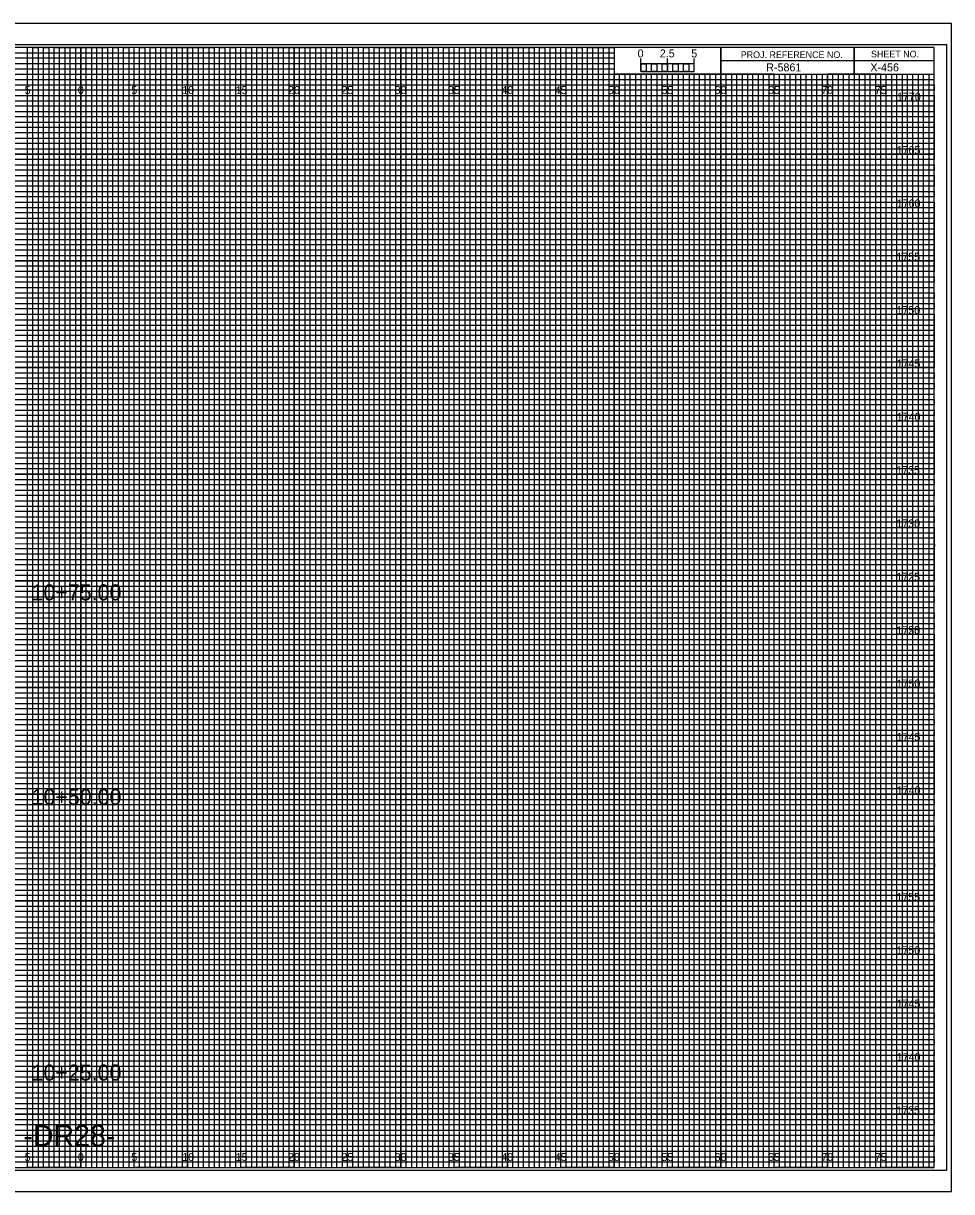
# Model space of a CAD drawing. Extents: x -7 to 162, y -2 to 547.
# Drawn here: x 74.6 to 161.7, y -2.3 to 107.3 of the extents above; entities that cross this region are included whole.
import ezdxf

# ---------------------------------------------------------------- set-up
doc = ezdxf.new("R2010")
doc.units = 0
for name, color, linetype in [('Prop Horizontal Alignment', 7, 'Continuous'), ('Prop XS Alignment Label', 7, 'Continuous'), ('Prop XS Bar Scale Labels', 7, 'Continuous'), ('Prop XS Gore Control Minimum', 7, 'Continuous'), ('Prop XS Project Number', 7, 'Continuous'), ('Prop XS Sheet Number', 7, 'Continuous'), ('Prop XS Shoulder Borrow Shape', 7, 'Continuous'), ('Raster_Level_0', 7, 'Continuous'), ('Scratch_Level_3', 7, 'Continuous'), ('Sheet Cross Section CELL', 7, 'Continuous'), ('Sheet Cross Section Grid Minor 1 CELL', 7, 'Continuous'), ('Sheet Cross Section Grid Minor 2 CELL', 7, 'Continuous'), ('Sheet Cross Section Scale CELL', 7, 'Continuous'), ('Sheet Cutting Line CELL', 7, 'Continuous'), ('Sheet DOT Grid CELL', 7, 'Continuous'), ('Sheet Plot Border Inside CELL', 7, 'Continuous'), ('Sheet Plot Border Outside CELL', 7, 'Continuous')]:
    doc.layers.add(name, color=color, linetype=linetype)

msp = doc.modelspace()

# ---------------------------------------------------------------- linework, layer by layer
at = {"layer": 'Prop XS Gore Control Minimum'}
for p, q in [((75, 105), (70, 105)), ((75, 0), (75, 105)), ((85, 105), (80, 105)), ((80, 105), (80, 0)), ((85, 0), (85, 105)), ((95, 105), (90, 105)), ((90, 105), (90, 0)), ((95, 0), (95, 105)), ((105, 105), (100, 105)), ((100, 105), (100, 0)), ((105, 0), (105, 105)), ((115, 105), (110, 105)), ((110, 105), (110, 0)), ((115, 0), (115, 105)), ((125, 105), (120, 105)), ((120, 105), (120, 0)), ((125, 0), (125, 105)), ((130, 105), (130, 0)), ((135, 0), (135, 102.5)), ((145, 102.5), (140, 102.5)), ((140, 102.5), (140, 0)), ((145, 0), (145, 102.5)), ((155, 102.5), (150, 102.5)), ((150, 102.5), (150, 0)), ((155, 0), (155, 102.5)), ((80, 0), (75, 0)), ((90, 0), (85, 0)), ((100, 0), (95, 0)), ((110, 0), (105, 0)), ((120, 0), (115, 0)), ((130, 0), (125, 0)), ((140, 0), (135, 0)), ((150, 0), (145, 0)), ((160, 0), (155, 0)), ((160, 0), (160, 0))]:
    msp.add_line(p, q, dxfattribs=at)
for points in [[(0, 100), (160, 100), (160, 95), (0, 95)], [(0, 90), (160, 90), (160, 85), (0, 85)], [(0, 80), (160, 80), (160, 75), (0, 75)], [(0, 70), (160, 70), (160, 65), (0, 65)], [(0, 60), (160, 60), (160, 55), (0, 55)], [(0, 50), (160, 50), (160, 45), (0, 45)], [(0, 40), (160, 40), (160, 35), (0, 35)], [(0, 30), (160, 30), (160, 25), (0, 25)], [(0, 20), (160, 20), (160, 15), (0, 15)], [(0, 10), (160, 10), (160, 5), (0, 5)]]:
    msp.add_lwpolyline(points, dxfattribs=at)
at = {"layer": 'Prop XS Shoulder Borrow Shape'}
for points in [[(72.5, 0), (77.5, 0), (77.5, 105), (82.5, 105), (82.5, 0), (87.5, 0), (87.5, 105), (92.5, 105), (92.5, 0), (97.5, 0), (97.5, 105), (102.5, 105), (102.5, 0), (107.5, 0), (107.5, 105), (112.5, 105), (112.5, 0), (117.5, 0), (117.5, 105), (122.5, 105), (122.5, 0), (127.5, 0), (127.5, 105), (129.97, 105), (130, 105), (130, 102.5), (132.5, 102.5), (132.5, 0), (137.5, 0), (137.5, 102.5), (142.5, 102.5), (142.5, 0), (147.5, 0), (147.5, 102.5), (152.5, 102.5), (152.5, 0), (157.5, 0), (157.5, 102.5)], [(0, 102.5), (137.5, 102.5)], [(0, 92.5), (160, 92.5), (160, 97.5), (0, 97.5)], [(0, 82.5), (160, 82.5), (160, 87.5), (0, 87.5)], [(0, 72.5), (160, 72.5), (160, 77.5), (0, 77.5)], [(0, 62.5), (160, 62.5), (160, 67.5), (0, 67.5)], [(0, 52.5), (160, 52.5), (160, 57.5), (0, 57.5)], [(0, 42.5), (160, 42.5), (160, 47.5), (0, 47.5)], [(0, 32.5), (160, 32.5), (160, 37.5), (0, 37.5)], [(0, 22.5), (160, 22.5), (160, 27.5), (0, 27.5)], [(0, 12.5), (160, 12.5), (160, 17.5), (0, 17.5)], [(0, 2.5), (160, 2.5), (160, 7.5), (0, 7.5)]]:
    msp.add_lwpolyline(points, dxfattribs=at)
at = {"layer": 'Sheet Cross Section CELL'}
for p, q in [((152.5, 105), (152.5, 102.5)), ((152.5, 102.5), (152.5, 105)), ((160, 103.75), (140, 103.75)), ((140, 103.75), (140, 102.5)), ((140, 102.5), (160, 102.5))]:
    msp.add_line(p, q, dxfattribs=at)
for points in [[(160, 105), (0, 105), (0, 0), (160, 0)], [(140, 105), (130, 105), (130, 102.52), (140, 102.52)], [(160, 105), (140, 105), (140, 102.5), (160, 102.5)]]:
    msp.add_lwpolyline(points, close=True, dxfattribs=at)
at = {"layer": 'Sheet Cross Section Grid Minor 1 CELL'}
for p, q in [((0, 104.5), (130, 104.5)), ((130, 104.5), (130, 103.99)), ((130, 103.99), (0, 103.99)), ((0, 103.5), (130, 103.5)), ((130, 102.95), (0, 102.95)), ((130, 103.5), (130, 102.95)), ((0, 102), (160, 102))]:
    msp.add_line(p, q, dxfattribs=at)
for points in [[(0, 101.5), (135, 101.5), (160, 101.5), (160, 101), (0, 101)], [(0, 100.5), (160, 100.5), (160, 99.5), (0, 99.5)], [(0, 99), (160, 99), (160, 98.5), (0, 98.49)], [(0, 98), (160, 98), (160, 97), (0, 97)], [(0, 96.5), (160, 96.5), (160, 96), (0, 96)], [(0, 95.5), (160, 95.5), (160, 94.5), (0, 94.5)], [(0, 94), (160, 94), (160, 93.5), (0, 93.5)], [(0, 93), (160, 93), (160, 92), (0, 92)], [(0, 91.5), (160, 91.5), (160, 91), (0, 91)], [(0, 90.5), (160, 90.5), (160, 89.5), (0, 89.5)], [(0, 89), (160, 89), (160, 88.5), (0, 88.5)], [(0, 88), (160, 88), (160, 86.98), (160, 86.5), (160, 86), (0, 86)], [(0, 87), (160, 87), (160, 86.5), (0, 86.5)], [(0, 85.5), (160, 85.5), (160, 84.5), (0, 84.52)], [(0, 84.52), (160, 84.5), (160, 84), (0, 84)], [(0, 83.5), (160, 83.5), (160, 83), (0, 83)], [(0, 82), (160, 82), (160, 81.5), (0, 81.5)], [(0, 81), (160, 81), (160, 80.5), (0, 80.5)], [(-0.04, 79.45), (160, 79.45), (160, 78.94), (-0.04, 78.94)], [(0, 78.5), (160, 78.5), (160, 78), (0, 78)], [(0, 77), (160, 77), (160, 76.5), (0, 76.5)], [(0, 76), (160, 76), (160, 75.5), (0, 75.5)], [(0, 74.5), (160, 74.5), (160, 74), (0, 74)], [(0, 73.5), (160, 73.5), (160, 73), (0, 73)], [(0, 72), (160, 72), (160, 71.5), (0, 71.5)], [(0, 71), (160, 71), (160, 70.5), (0, 70.5)], [(0, 69.5), (160, 69.5), (160, 68.99), (0, 69)], [(0, 68.5), (160, 68.5), (160, 68), (0, 68)], [(0, 67), (160, 67), (160, 66.5), (0, 66.5)], [(0, 66), (160, 66), (160, 65.5), (0, 65.5)], [(0, 64.5), (160, 64.5), (160, 64), (0, 64)], [(0, 63.5), (160, 63.5), (160, 63), (0, 63)], [(0, 62), (160, 62), (160, 61.5), (0, 61.5)], [(0, 61), (160, 61), (160, 60.5), (0, 60.5)], [(0, 59.5), (160, 59.5), (160, 59), (0, 59)], [(0, 58.5), (160.03, 58.45), (160, 58), (0, 58)], [(0, 57), (160, 57), (160, 56.5), (0, 56.5)], [(0, 56), (160, 56), (160, 55.5), (0, 55.5)], [(0, 54.5), (160, 54.5), (160, 54), (0, 54)], [(0, 53.5), (160, 53.5), (160, 53), (0, 53)], [(0, 52), (160, 52), (160, 51.5), (0, 51.5)], [(0, 51), (160, 51), (160, 50.5), (0, 50.5)], [(0, 49.5), (160, 49.5), (160, 49), (0, 49)], [(0, 48.5), (160, 48.5), (160, 48), (0, 48)], [(0, 47), (160, 47), (160, 46.5), (0, 46.5)], [(0, 46), (160, 46), (160, 45.5), (0, 45.5)], [(0, 44.5), (160, 44.5), (160, 44), (0, 44)], [(0, 43.5), (160, 43.5), (160, 43), (0, 43)], [(0, 42), (160, 42), (160, 41.5), (0, 41.5)], [(0, 41), (160, 41), (160, 40.5), (0, 40.5)], [(0, 39.5), (160, 39.5), (160, 38.99), (0, 39)], [(0, 38.5), (160, 38.5), (160, 38), (0, 38)], [(0, 37), (160, 37), (160, 36.5), (0, 36.5)], [(0, 36), (160, 36), (160, 35.5), (0, 35.5)], [(0, 34.5), (160, 34.5), (160, 34), (0, 34)], [(0, 33.5), (160, 33.5), (160, 33), (0, 33)], [(0, 32), (160, 32), (160, 31.5), (0, 31.5)], [(0, 31), (160, 31), (160, 30.5), (0, 30.5)], [(0, 29.5), (160, 29.5), (160, 29), (0, 29)], [(0, 28.5), (160.03, 28.46), (160, 28), (0, 28)], [(0, 27), (160, 27), (160, 26.5), (0, 26.5)], [(0, 26), (160, 26), (160, 25.5), (0, 25.5)], [(0, 24.5), (160, 24.5), (160, 24), (0, 24)], [(0, 23.5), (160, 23.5), (160, 23), (0, 23)], [(0, 22), (160, 22), (160, 21.5), (0, 21.5)], [(0, 21), (160, 21), (160, 20.5), (0, 20.5)], [(0, 19.5), (160, 19.5), (160, 19), (0, 19)], [(0, 18.5), (160, 18.5), (160, 18), (0, 18)], [(0, 17), (160, 17), (160, 16.5), (0, 16.5)], [(0, 16), (160, 16), (160, 15.5), (0, 15.5)], [(0, 14.5), (160, 14.5), (160, 14), (0, 14)], [(0, 13.5), (160, 13.5), (160, 13), (0, 13)], [(0, 12), (160, 12), (160, 11.5), (0, 11.5)], [(0, 11), (160, 11), (160, 10.5), (0, 10.5)], [(0, 9.5), (160, 9.5), (160, 9), (0, 9)], [(0, 8.5), (160, 8.5), (160, 8), (0, 8)], [(0, 7), (160, 7), (160, 6.5), (0, 6.5)], [(0, 6), (160, 6), (160, 5.5), (0, 5.5)], [(0, 4.5), (160, 4.5), (160, 4), (0, 4)], [(0, 3.5), (160, 3.5), (160, 3), (0, 3)], [(0, 2), (160, 2), (160, 1.5), (0, 1.5)], [(0, 1), (160, 1), (160, 0.5), (0, 0.5)]]:
    msp.add_lwpolyline(points, dxfattribs=at)
at = {"layer": 'Sheet Cross Section Grid Minor 2 CELL'}
for p, q in [((133.5, 102.5), (133, 102.5)), ((133, 102.5), (133, 0)), ((133.5, 0), (133.5, 102.5)), ((134.5, 102.5), (134, 102.5)), ((134, 102.5), (134, 0)), ((134.5, 0), (134.5, 102.5)), ((133, 0), (132.5, 0)), ((134, 0), (133.5, 0))]:
    msp.add_line(p, q, dxfattribs=at)
for points in [[(75, 0), (75.5, 0), (75.5, 105), (76, 105), (76, 0)], [(76, 0), (76.5, 0), (76.5, 105), (77, 105), (77, 0)], [(77.5, 0), (78, 0), (78, 105), (78.5, 105), (78.5, 0)], [(78.5, 0), (79, 0), (79, 105), (79.5, 105), (79.5, 0)], [(80, 0), (80.5, 0), (80.5, 105), (81, 105), (81, 0)], [(81, 0), (81.5, 0), (81.5, 105), (82, 105), (82, 0)], [(82.5, 0), (83, 0), (83, 105), (83.5, 105), (83.5, 0)], [(83.5, 0), (84, 0), (84, 105), (84.5, 105), (84.5, 0)], [(85, 0), (85.5, 0), (85.5, 105), (86, 105), (86, 0)], [(86, 0), (86.5, 0), (86.5, 105), (87, 105), (87, 0)], [(87.5, 0), (88, 0), (88, 105), (88.5, 105), (88.5, 0)], [(88.5, 0), (89, 0), (89, 105), (89.5, 105), (89.5, 0)], [(90, 0), (90.5, 0), (90.5, 105), (91, 105), (91, 0)], [(91, 0), (91.5, 0), (91.5, 105), (92, 105), (92, 0)], [(92.5, 0), (93, 0), (93, 105), (93.5, 105), (93.5, 0)], [(93.5, 0), (94, 0), (94, 105), (94.5, 105), (94.5, 0)], [(95, 0), (95.5, 0), (95.5, 105), (96, 105), (96, 0)], [(96, 0), (96.5, 0), (96.5, 105), (97, 105), (97, 0)], [(97.5, 0), (98, 0), (98, 105), (98.5, 105), (98.5, 0)], [(98.5, 0), (99, 0), (99, 105), (99.5, 105), (99.5, 0)], [(100, 0), (100.5, 0), (100.5, 105), (101, 105), (101, 0)], [(101, 0), (101.5, 0), (101.5, 105), (102, 105), (102, 0)], [(102.5, 0), (103, 0), (103, 105), (103.5, 105), (103.5, 0)], [(103.5, 0), (104, 0), (104, 105), (104.5, 105), (104.5, 0)], [(105, 0), (105.5, 0), (105.5, 105), (106, 105), (106, 0)], [(106, 0), (106.5, 0), (106.5, 105), (107, 105), (107, 0)], [(107.5, 0), (108, 0), (108, 105), (108.5, 105), (108.5, 0)], [(108.5, 0), (109, 0), (109, 105), (109.5, 105), (109.5, 0)], [(110, 0), (110.5, 0), (110.5, 105), (111, 105), (111, 0)], [(111, 0), (111.5, 0), (111.5, 105), (112, 105), (112, 0)], [(112.5, 0), (113, 0), (113, 105), (113.5, 105), (113.5, 0)], [(113.5, 0), (114, 0), (114, 105), (114.5, 105), (114.5, 0)], [(115, 0), (115.5, 0), (115.5, 105), (116, 105), (116, 0)], [(116, 0), (116.5, 0), (116.5, 105), (117, 105), (117, 0)], [(117.5, 0), (118, 0), (118, 105), (118.5, 105), (118.5, 0)], [(118.5, 0), (119, 0), (119, 105), (119.5, 105), (119.5, 0)], [(120, 0), (120.5, 0), (120.5, 105), (121, 105), (121, 0)], [(121, 0), (121.5, 0), (121.5, 105), (122, 105), (122, 0)], [(122.5, 0), (123, 0), (123, 105), (123.5, 105), (123.5, 0)], [(123.5, 0), (124, 0), (124, 105), (124.5, 105), (124.5, 0)], [(125, 0), (125.5, 0), (125.5, 105), (126, 105), (126, 0)], [(126, 0), (126.5, 0), (126.5, 105), (127, 105), (127, 0)], [(127.5, 0), (128, 0), (128, 105), (128.5, 105), (128.5, 0)], [(128.5, 0), (129, 0), (129, 105), (129.5, 105), (129.5, 0)], [(130, 0), (130.5, 0), (130.5, 102.5), (131.01, 102.5), (131.01, 0)], [(131, 0), (131.5, 0), (131.5, 102.5), (132, 102.5), (132, 0)], [(135, 0), (135.49, 0), (135.49, 102.5), (136, 102.5), (136, 0)], [(136, 0), (136.5, 0), (136.5, 102.5), (137.03, 102.5), (137.03, 0)], [(137.5, 0), (138, 0), (138, 102.5), (138.5, 102.5), (138.5, 0)], [(138.5, 0), (139, 0), (139, 102.5), (139.5, 102.5), (139.5, 0)], [(140, 0), (140.5, 0), (140.5, 102.5), (141, 102.5), (141, 0)], [(141, 0), (141.5, 0), (141.5, 102.5), (142, 102.5), (142, 0)], [(142.5, 0), (143, 0), (143, 102.5), (143.5, 102.5), (143.5, 0)], [(143.5, 0), (144, 0), (144, 102.5), (144.5, 102.5), (144.5, 0)], [(145, 0), (145.5, 0), (145.5, 102.5), (146, 102.5), (146, 0)], [(146, 0), (146.5, 0), (146.5, 102.5), (147, 102.5), (147, 0)], [(147.5, 0), (148, 0), (148, 102.5), (148.5, 102.5), (148.5, 0)], [(148.5, 0), (149, 0), (149, 102.5), (149.5, 102.5), (149.5, 0)], [(150, 0), (150.5, 0), (150.5, 102.5), (151, 102.5), (151, 0)], [(151, 0), (151.5, 0), (151.5, 102.5), (152, 102.5), (152, 0)], [(152.5, 0), (153, 0), (153, 102.5), (153.5, 102.5), (153.5, 0)], [(153.5, 0), (154, 0), (154, 102.5), (154.5, 102.5), (154.5, 0)], [(155, 0), (155.5, 0), (155.5, 102.5), (156, 102.5), (156, 0)], [(156, 0), (156.5, 0), (156.5, 102.5), (157, 102.5), (157, 0)], [(157.5, 0), (158, 0), (158, 102.5), (158.5, 102.5), (158.5, 0)], [(158.5, 0), (159, 0), (159, 102.5), (159.5, 102.5), (159.5, 0)]]:
    msp.add_lwpolyline(points, dxfattribs=at)
at = {"layer": 'Sheet Cross Section Scale CELL'}
for p, q in [((132.5, 102.75), (132.5, 103.95)), ((132.5, 103.45), (132.5, 103.95)), ((135, 102.75), (135, 103.95)), ((137.5, 102.75), (137.5, 103.95)), ((137.5, 103.45), (137.5, 103.95))]:
    msp.add_line(p, q, dxfattribs=at)
for points in [[(137.5, 103.45), (132.5, 103.45), (132.5, 102.75), (137.5, 102.75)], [(132.5, 103.45), (133, 103.45), (133, 102.75), (132.5, 102.75)], [(133.5, 103.45), (134, 103.45), (134, 102.75), (133.5, 102.75)], [(134.5, 103.45), (135, 103.45), (135, 102.75), (134.5, 102.75)], [(135.5, 103.45), (136, 103.45), (136, 102.75), (135.5, 102.75)], [(136.5, 103.45), (137, 103.45), (137, 102.75), (136.5, 102.75)]]:
    msp.add_lwpolyline(points, close=True, dxfattribs=at)
at = {"layer": 'Sheet Cutting Line CELL'}
for p, q in [((161.65, 107.25), (-6.7, 107.25)), ((-6.7, -2.25), (161.65, -2.25))]:
    msp.add_line(p, q, dxfattribs=at)
at = {"layer": 'Sheet DOT Grid CELL'}
for p, q in [((75, 0), (75, 105)), ((80, 0), (80, 105)), ((85, 0), (85, 105)), ((90, 0), (90, 105)), ((95, 0), (95, 105)), ((100, 0), (100, 105)), ((105, 0), (105, 105)), ((110, 0), (110, 105)), ((115, 0), (115, 105)), ((120, 0), (120, 105)), ((125, 0), (125, 105)), ((130, 0), (130, 102.34)), ((135, 0), (135, 102.34)), ((140, 0), (140, 102.34)), ((145, 0), (145, 102.34)), ((150, 0), (150, 102.34)), ((155, 0), (155, 102.34)), ((0, 100), (160, 100)), ((0, 95), (160, 95)), ((0, 90), (160, 90)), ((0, 85), (160, 85)), ((0, 80), (160, 80)), ((0, 75), (160, 75)), ((0, 70), (160, 70)), ((0, 65), (160, 65)), ((0, 60), (160, 60)), ((0, 55), (160, 55)), ((0, 50), (160, 50)), ((0, 45), (160, 45)), ((0, 40), (160, 40)), ((0, 35), (160, 35)), ((0, 30), (160, 30)), ((0, 25), (160, 25)), ((0, 20), (160, 20)), ((0, 15), (160, 15)), ((0, 10), (160, 10)), ((0, 5), (160, 5))]:
    msp.add_line(p, q, dxfattribs=at)
at = {"layer": 'Sheet Plot Border Inside CELL'}
msp.add_lwpolyline([(-5.4, -0.25), (161.2, -0.25), (161.2, 105.25), (-5.4, 105.25)], close=True, dxfattribs=at)
at = {"layer": 'Sheet Plot Border Outside CELL'}
msp.add_lwpolyline([(-6.7, -2.25), (161.65, -2.25), (161.65, 107.25), (-6.7, 107.25)], close=True, dxfattribs=at)

# ---------------------------------------------------------------- texts
at = {"layer": 'Prop Horizontal Alignment'}
for s, p in [('10+75.00', (75.39, 53.17)), ('10+50.00', (75.39, 34)), ('10+25.00', (75.39, 8.16))]:
    msp.add_text(s, height=1.5, dxfattribs=at).set_placement(p)
at = {"layer": 'Prop XS Alignment Label'}
msp.add_text('-DR28-', height=2, dxfattribs=at).set_placement((74.62, 2))
at = {"layer": 'Prop XS Bar Scale Labels'}
for s, p in [('2.5', (134.29, 104.06)), ('5', (137.24, 104.06))]:
    msp.add_text(s, height=0.75, dxfattribs=at).set_placement(p)
at = {"layer": 'Prop XS Project Number'}
msp.add_text('R-5861', height=0.75, dxfattribs=at).set_placement((144.27, 102.75))
at = {"layer": 'Prop XS Sheet Number'}
msp.add_text('X-456', height=0.75, dxfattribs=at).set_placement((154.03, 102.75))
at = {"layer": 'Raster_Level_0'}
for s, p in [('5', (74.74, 100.62)), ('0', (79.73, 100.62)), ('0', (79.73, 100.62)), ('5', (84.74, 100.62)), ('10', (89.52, 100.62)), ('15', (94.53, 100.62)), ('20', (99.43, 100.62)), ('25', (104.44, 100.62)), ('30', (109.43, 100.62)), ('35', (114.44, 100.62)), ('40', (119.43, 100.62)), ('45', (124.44, 100.62)), ('50', (129.43, 100.62)), ('55', (134.44, 100.62)), ('60', (139.43, 100.62)), ('65', (144.44, 100.62)), ('70', (149.43, 100.62)), ('75', (154.44, 100.62)), ('5', (74.74, 0.62)), ('0', (79.73, 0.62)), ('0', (79.73, 0.62)), ('5', (84.74, 0.62)), ('10', (89.52, 0.62)), ('15', (94.53, 0.62)), ('20', (99.43, 0.62)), ('25', (104.44, 0.62)), ('30', (109.43, 0.62)), ('35', (114.44, 0.62)), ('40', (119.43, 0.62)), ('45', (124.44, 0.62)), ('50', (129.43, 0.62)), ('55', (134.44, 0.62)), ('60', (139.43, 0.62)), ('65', (144.44, 0.62)), ('70', (149.43, 0.62)), ('75', (154.44, 0.62))]:
    msp.add_text(s, height=0.75, dxfattribs=at).set_placement(p)
at = {"layer": 'Scratch_Level_3'}
for s, p in [('1770', (156.52, 100)), ('1765', (156.49, 95)), ('1760', (156.5, 90)), ('1755', (156.47, 85)), ('1750', (156.48, 80)), ('1745', (156.49, 75)), ('1740', (156.5, 70)), ('1735', (156.45, 65)), ('1730', (156.46, 60)), ('1725', (156.46, 55)), ('1720', (156.47, 50)), ('1755', (156.47, 50)), ('1750', (156.48, 45)), ('1745', (156.49, 40)), ('1740', (156.5, 35)), ('1755', (156.47, 25)), ('1750', (156.48, 20)), ('1745', (156.49, 15)), ('1740', (156.5, 10)), ('1735', (156.45, 5))]:
    msp.add_text(s, height=0.75, dxfattribs=at).set_placement(p)
at = {"layer": 'Sheet Cross Section CELL'}
for s, p in [('PROJ. REFERENCE NO.', (141.88, 104)), ('SHEET NO.', (154.09, 104.06))]:
    msp.add_text(s, height=0.625, dxfattribs=at).set_placement(p)
at = {"layer": 'Sheet Cross Section Scale CELL'}
msp.add_text('0', height=0.75, dxfattribs=at).set_placement((132.21, 104.06))

doc.saveas('drawing.dxf')
